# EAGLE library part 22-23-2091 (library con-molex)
.100" (2.54mm) Center Header - 9 Pin
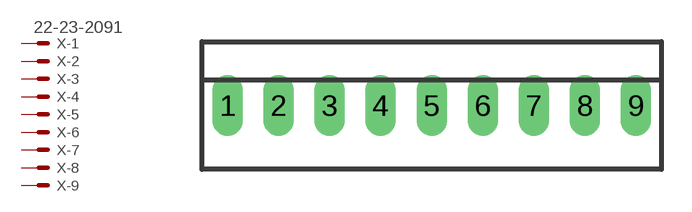
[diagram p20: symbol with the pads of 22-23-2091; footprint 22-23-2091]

Designator prefix X; gates -1=MV -2=M -3=M -4=M -5=M -6=M -7=M -8=M -9=M

## 22-23-2091 (MF: MOLEX; MPN: 22-23-2091; OC_FARNELL: 1756827; OC_NEWARK: 56H0450)  [22-23-2091]
1  -1:S  pas
2  -2:S  pas
3  -3:S  pas
4  -4:S  pas
5  -5:S  pas
6  -6:S  pas
7  -7:S  pas
8  -8:S  pas
9  -9:S  pas

## Footprint 22-23-2091 (pad centres in mm)
.100" (2.54mm) Center Header - 9 Pin
drill 1 long: 1 -10.16,0; 2 -7.62,0; 3 -5.08,0; 4 -2.54,0; 5 0,0; 6 2.54,0; 7 5.08,0; 8 7.62,0; 9 10.16,0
